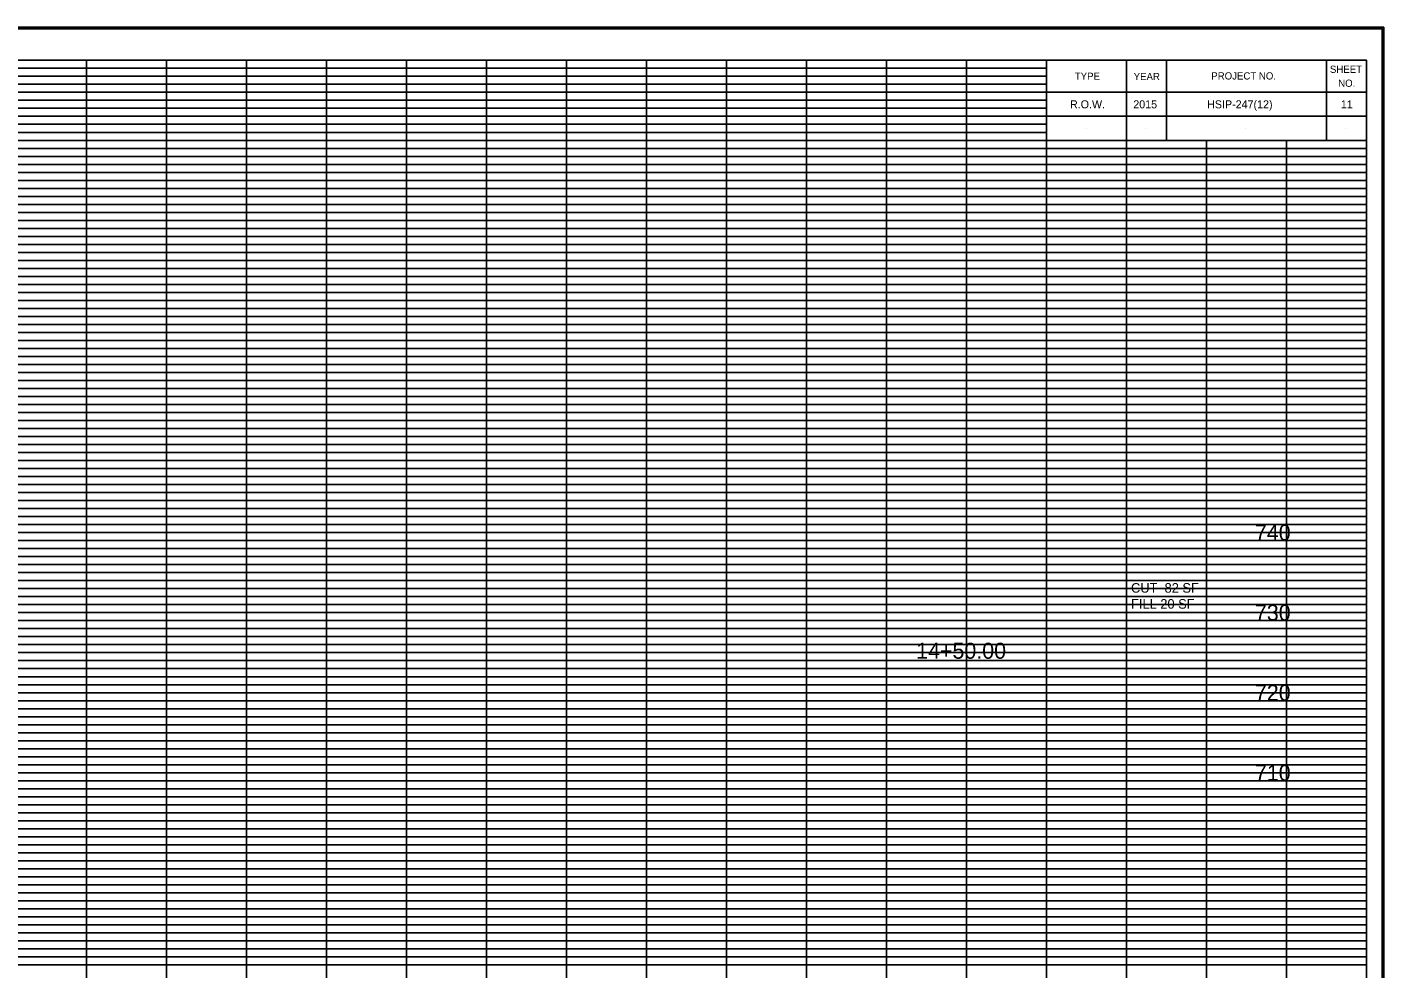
# Model space of a CAD drawing. Extents: x -200 to 1704, y -325 to 2307.
# Drawn here: x 1152.6 to 1322.2, y 1366.5 to 1484.1 of the extents above; entities that cross this region are included whole.
import ezdxf

# ---------------------------------------------------------------- set-up
doc = ezdxf.new("R2010")
doc.units = 0
for name, color, linetype in [('DESIGN - SCRATCH - User 1', 7, 'Continuous'), ('DESIGN - SHEET - Corner Text', 7, 'Continuous'), ('DESIGN - SHEET - Light Grid', 7, 'Continuous'), ('DESIGN - SHEET - Linework', 7, 'Continuous'), ('DESIGN - SHEET - Plot Shape', 7, 'Continuous'), ('DESIGN - TYPICAL - Text', 7, 'Continuous')]:
    doc.layers.add(name, color=color, linetype=linetype)

msp = doc.modelspace()

# ---------------------------------------------------------------- linework, layer by layer
at = {"layer": 'DESIGN - SCRATCH - User 1'}
for p, q in [((1285, 1474.5), (1285, 1474.5)), ((1292.4, 1474.5), (1292.4, 1474.5)), ((1304.9, 1474.5), (1304.9, 1474.5)), ((1317.4, 1474.5), (1317.4, 1474.5)), ((1285, 1471.5), (1285, 1471.5)), ((1292.4, 1471.5), (1292.4, 1471.5)), ((1304.9, 1471.5), (1304.9, 1471.5)), ((1317.4, 1471.5), (1317.4, 1471.5))]:
    msp.add_line(p, q, dxfattribs=at)
at = {"layer": 'DESIGN - SHEET - Light Grid'}
for p, q in [((1080, 1479), (1160, 1479)), ((1160, 1479), (1240, 1479)), ((1240, 1479), (1280, 1479)), ((1080, 1478), (1160, 1478)), ((1160, 1478), (1240, 1478)), ((1240, 1478), (1280, 1478)), ((1080, 1477), (1160, 1477)), ((1080, 1476), (1160, 1476)), ((1160, 1477), (1240, 1477)), ((1160, 1476), (1240, 1476)), ((1240, 1477), (1280, 1477)), ((1240, 1476), (1280, 1476)), ((1080, 1475), (1160, 1475)), ((1080, 1474), (1160, 1474)), ((1160, 1475), (1240, 1475)), ((1160, 1474), (1240, 1474)), ((1240, 1475), (1280, 1475)), ((1240, 1474), (1280, 1474)), ((1080, 1473), (1160, 1473)), ((1080, 1472), (1160, 1472)), ((1160, 1473), (1240, 1473)), ((1160, 1472), (1240, 1472)), ((1240, 1473), (1280, 1473)), ((1240, 1472), (1280, 1472)), ((1080, 1471), (1160, 1471)), ((1160, 1471), (1240, 1471)), ((1240, 1471), (1280, 1471)), ((1080, 1469), (1160, 1469)), ((1160, 1469), (1240, 1469)), ((1240, 1469), (1320, 1469)), ((1080, 1468), (1160, 1468)), ((1080, 1467), (1160, 1467)), ((1160, 1468), (1240, 1468)), ((1160, 1467), (1240, 1467)), ((1240, 1468), (1320, 1468)), ((1240, 1467), (1320, 1467)), ((1080, 1466), (1160, 1466)), ((1160, 1466), (1240, 1466)), ((1240, 1466), (1320, 1466)), ((1080, 1465), (1160, 1465)), ((1080, 1464), (1160, 1464)), ((1160, 1465), (1240, 1465)), ((1160, 1464), (1240, 1464)), ((1240, 1465), (1320, 1465)), ((1240, 1464), (1320, 1464)), ((1080, 1463), (1160, 1463)), ((1080, 1462), (1160, 1462)), ((1160, 1463), (1240, 1463)), ((1160, 1462), (1240, 1462)), ((1240, 1463), (1320, 1463)), ((1240, 1462), (1320, 1462)), ((1080, 1461), (1160, 1461)), ((1160, 1461), (1240, 1461)), ((1240, 1461), (1320, 1461)), ((1080, 1459), (1160, 1459)), ((1160, 1459), (1240, 1459)), ((1240, 1459), (1320, 1459)), ((1080, 1458), (1160, 1458)), ((1080, 1457), (1160, 1457)), ((1160, 1458), (1240, 1458)), ((1160, 1457), (1240, 1457)), ((1240, 1458), (1320, 1458)), ((1240, 1457), (1320, 1457)), ((1080, 1456), (1160, 1456)), ((1080, 1455), (1160, 1455)), ((1160, 1456), (1240, 1456)), ((1160, 1455), (1240, 1455)), ((1240, 1456), (1320, 1456)), ((1240, 1455), (1320, 1455)), ((1080, 1454), (1160, 1454)), ((1160, 1454), (1240, 1454)), ((1240, 1454), (1320, 1454)), ((1080, 1453), (1160, 1453)), ((1080, 1452), (1160, 1452)), ((1160, 1453), (1240, 1453)), ((1160, 1452), (1240, 1452)), ((1240, 1453), (1320, 1453)), ((1240, 1452), (1320, 1452)), ((1080, 1451), (1160, 1451)), ((1160, 1451), (1240, 1451)), ((1240, 1451), (1320, 1451)), ((1080, 1449), (1160, 1449)), ((1160, 1449), (1240, 1449)), ((1240, 1449), (1320, 1449)), ((1080, 1448), (1160, 1448)), ((1080, 1447), (1160, 1447)), ((1160, 1448), (1240, 1448)), ((1160, 1447), (1240, 1447)), ((1240, 1448), (1320, 1448)), ((1240, 1447), (1320, 1447)), ((1080, 1446), (1160, 1446)), ((1080, 1445), (1160, 1445)), ((1160, 1446), (1240, 1446)), ((1160, 1445), (1240, 1445)), ((1240, 1446), (1320, 1446)), ((1240, 1445), (1320, 1445)), ((1080, 1444), (1160, 1444)), ((1160, 1444), (1240, 1444)), ((1240, 1444), (1320, 1444)), ((1080, 1443), (1160, 1443)), ((1080, 1442), (1160, 1442)), ((1160, 1443), (1240, 1443)), ((1160, 1442), (1240, 1442)), ((1240, 1443), (1320, 1443)), ((1240, 1442), (1320, 1442)), ((1080, 1441), (1160, 1441)), ((1160, 1441), (1240, 1441)), ((1240, 1441), (1320, 1441)), ((1080, 1439), (1160, 1439)), ((1160, 1439), (1240, 1439)), ((1240, 1439), (1320, 1439)), ((1080, 1438), (1160, 1438)), ((1080, 1437), (1160, 1437)), ((1160, 1438), (1240, 1438)), ((1160, 1437), (1240, 1437)), ((1240, 1438), (1320, 1438)), ((1240, 1437), (1320, 1437)), ((1080, 1436), (1160, 1436)), ((1080, 1435), (1160, 1435)), ((1160, 1436), (1240, 1436)), ((1160, 1435), (1240, 1435)), ((1240, 1436), (1320, 1436)), ((1240, 1435), (1320, 1435)), ((1080, 1434), (1160, 1434)), ((1080, 1433), (1160, 1433)), ((1160, 1434), (1240, 1434)), ((1160, 1433), (1240, 1433)), ((1240, 1434), (1320, 1434)), ((1240, 1433), (1320, 1433)), ((1080, 1432), (1160, 1432)), ((1160, 1432), (1240, 1432)), ((1240, 1432), (1320, 1432)), ((1080, 1431), (1160, 1431)), ((1160, 1431), (1240, 1431)), ((1240, 1431), (1320, 1431)), ((1080, 1429), (1160, 1429)), ((1080, 1428), (1160, 1428)), ((1160, 1429), (1240, 1429)), ((1160, 1428), (1240, 1428)), ((1240, 1429), (1320, 1429)), ((1240, 1428), (1320, 1428)), ((1080, 1427), (1160, 1427)), ((1160, 1427), (1240, 1427)), ((1240, 1427), (1320, 1427)), ((1080, 1426), (1160, 1426)), ((1080, 1425), (1160, 1425)), ((1160, 1426), (1240, 1426)), ((1160, 1425), (1240, 1425)), ((1240, 1426), (1320, 1426)), ((1240, 1425), (1320, 1425)), ((1080, 1424), (1160, 1424)), ((1080, 1423), (1160, 1423)), ((1160, 1424), (1240, 1424)), ((1160, 1423), (1240, 1423)), ((1240, 1424), (1320, 1424)), ((1240, 1423), (1320, 1423)), ((1080, 1422), (1160, 1422)), ((1160, 1422), (1240, 1422)), ((1240, 1422), (1320, 1422)), ((1080, 1421), (1160, 1421)), ((1160, 1421), (1240, 1421)), ((1240, 1421), (1320, 1421)), ((1080, 1419), (1160, 1419)), ((1080, 1418), (1160, 1418)), ((1160, 1419), (1240, 1419)), ((1160, 1418), (1240, 1418)), ((1240, 1419), (1320, 1419)), ((1240, 1418), (1320, 1418)), ((1080, 1417), (1160, 1417)), ((1080, 1416), (1160, 1416)), ((1160, 1417), (1240, 1417)), ((1160, 1416), (1240, 1416)), ((1240, 1417), (1320, 1417)), ((1240, 1416), (1320, 1416)), ((1080, 1415), (1160, 1415)), ((1160, 1415), (1240, 1415)), ((1240, 1415), (1320, 1415)), ((1080, 1414), (1160, 1414)), ((1080, 1413), (1160, 1413)), ((1160, 1414), (1240, 1414)), ((1160, 1413), (1240, 1413)), ((1240, 1414), (1320, 1414)), ((1240, 1413), (1320, 1413)), ((1080, 1412), (1160, 1412)), ((1080, 1411), (1160, 1411)), ((1160, 1412), (1240, 1412)), ((1160, 1411), (1240, 1411)), ((1240, 1412), (1320, 1412)), ((1240, 1411), (1320, 1411)), ((1080, 1409), (1160, 1409)), ((1080, 1408), (1160, 1408)), ((1160, 1409), (1240, 1409)), ((1160, 1408), (1240, 1408)), ((1240, 1409), (1320, 1409)), ((1240, 1408), (1320, 1408)), ((1080, 1407), (1160, 1407)), ((1080, 1406), (1160, 1406)), ((1160, 1407), (1240, 1407)), ((1160, 1406), (1240, 1406)), ((1240, 1407), (1320, 1407)), ((1240, 1406), (1320, 1406)), ((1080, 1405), (1160, 1405)), ((1160, 1405), (1240, 1405)), ((1240, 1405), (1320, 1405)), ((1080, 1404), (1160, 1404)), ((1080, 1403), (1160, 1403)), ((1160, 1404), (1240, 1404)), ((1160, 1403), (1240, 1403)), ((1240, 1404), (1320, 1404)), ((1240, 1403), (1320, 1403)), ((1080, 1402), (1160, 1402)), ((1080, 1401), (1160, 1401)), ((1160, 1402), (1240, 1402)), ((1160, 1401), (1240, 1401)), ((1240, 1402), (1320, 1402)), ((1240, 1401), (1320, 1401)), ((1080, 1399), (1160, 1399)), ((1080, 1398), (1160, 1398)), ((1160, 1399), (1240, 1399)), ((1160, 1398), (1240, 1398)), ((1240, 1399), (1320, 1399)), ((1240, 1398), (1320, 1398)), ((1080, 1397), (1160, 1397)), ((1080, 1396), (1160, 1396)), ((1160, 1397), (1240, 1397)), ((1160, 1396), (1240, 1396)), ((1240, 1397), (1320, 1397)), ((1240, 1396), (1320, 1396)), ((1080, 1395), (1160, 1395)), ((1080, 1394), (1160, 1394)), ((1160, 1395), (1240, 1395)), ((1160, 1394), (1240, 1394)), ((1240, 1395), (1320, 1395)), ((1240, 1394), (1320, 1394)), ((1080, 1393), (1160, 1393)), ((1160, 1393), (1240, 1393)), ((1240, 1393), (1320, 1393)), ((1080, 1392), (1160, 1392)), ((1080, 1391), (1160, 1391)), ((1160, 1392), (1240, 1392)), ((1160, 1391), (1240, 1391)), ((1240, 1392), (1320, 1392)), ((1240, 1391), (1320, 1391)), ((1080, 1389), (1160, 1389)), ((1160, 1389), (1240, 1389)), ((1240, 1389), (1320, 1389)), ((1080, 1388), (1160, 1388)), ((1160, 1388), (1240, 1388)), ((1240, 1388), (1320, 1388)), ((1080, 1387), (1160, 1387)), ((1080, 1386), (1160, 1386)), ((1160, 1387), (1240, 1387)), ((1160, 1386), (1240, 1386)), ((1240, 1387), (1320, 1387)), ((1240, 1386), (1320, 1386)), ((1080, 1385), (1160, 1385)), ((1080, 1384), (1160, 1384)), ((1160, 1385), (1240, 1385)), ((1160, 1384), (1240, 1384)), ((1240, 1385), (1320, 1385)), ((1240, 1384), (1320, 1384)), ((1080, 1383), (1160, 1383)), ((1160, 1383), (1240, 1383)), ((1240, 1383), (1320, 1383)), ((1080, 1382), (1160, 1382)), ((1080, 1381), (1160, 1381)), ((1160, 1382), (1240, 1382)), ((1160, 1381), (1240, 1381)), ((1240, 1382), (1320, 1382)), ((1240, 1381), (1320, 1381)), ((1080, 1379), (1160, 1379)), ((1160, 1379), (1240, 1379)), ((1240, 1379), (1320, 1379)), ((1080, 1378), (1160, 1378)), ((1080, 1377), (1160, 1377)), ((1160, 1378), (1240, 1378)), ((1160, 1377), (1240, 1377)), ((1240, 1378), (1320, 1378)), ((1240, 1377), (1320, 1377)), ((1080, 1376), (1160, 1376)), ((1160, 1376), (1240, 1376)), ((1240, 1376), (1320, 1376)), ((1080, 1375), (1160, 1375)), ((1080, 1374), (1160, 1374)), ((1160, 1375), (1240, 1375)), ((1160, 1374), (1240, 1374)), ((1240, 1375), (1320, 1375)), ((1240, 1374), (1320, 1374)), ((1080, 1373), (1160, 1373)), ((1080, 1372), (1160, 1372)), ((1160, 1373), (1240, 1373)), ((1160, 1372), (1240, 1372)), ((1240, 1373), (1320, 1373)), ((1240, 1372), (1320, 1372)), ((1080, 1371), (1160, 1371)), ((1160, 1371), (1240, 1371)), ((1240, 1371), (1320, 1371)), ((1080, 1369), (1160, 1369)), ((1160, 1369), (1240, 1369)), ((1240, 1369), (1320, 1369)), ((1080, 1368), (1160, 1368)), ((1080, 1367), (1160, 1367)), ((1160, 1368), (1240, 1368)), ((1160, 1367), (1240, 1367)), ((1240, 1368), (1320, 1368)), ((1240, 1367), (1320, 1367))]:
    msp.add_line(p, q, dxfattribs=at)
at = {"layer": 'DESIGN - SHEET - Linework'}
for p, q in [((981.77, 1484.14), (1322.17, 1484.14)), ((1322.17, 1484.14), (1322.17, 1265.86)), ((1160, 1270), (1160, 1480)), ((1170, 1270), (1170, 1480)), ((1180, 1270), (1180, 1480)), ((1190, 1270), (1190, 1480)), ((1200, 1270), (1200, 1480)), ((1210, 1270), (1210, 1480)), ((1220, 1270), (1220, 1480)), ((1230, 1270), (1230, 1480)), ((1240, 1270), (1240, 1480)), ((1250, 1270), (1250, 1480)), ((1260, 1270), (1260, 1480)), ((1270, 1270), (1270, 1480)), ((1000, 1470), (1280, 1470)), ((1280, 1270), (1280, 1470)), ((1290, 1270), (1290, 1470)), ((1300, 1270), (1300, 1470)), ((1310, 1270), (1310, 1470)), ((1000, 1460), (1320, 1460)), ((1000, 1450), (1320, 1450)), ((1000, 1440), (1320, 1440)), ((1000, 1430), (1320, 1430)), ((1000, 1420), (1320, 1420)), ((1000, 1410), (1320, 1410)), ((1000, 1400), (1320, 1400)), ((1000, 1390), (1320, 1390)), ((1000, 1380), (1320, 1380)), ((1000, 1370), (1320, 1370))]:
    msp.add_line(p, q, dxfattribs=at)
for points in [[(1000, 1480), (1000, 1270), (1320, 1270), (1320, 1480), (1000, 1480)], [(1280, 1480), (1280, 1470), (1320, 1470), (1320, 1480), (1315, 1480), (1315, 1470), (1295, 1470), (1295, 1480), (1290, 1480), (1290, 1470), (1320, 1470), (1280, 1470), (1280, 1473), (1320, 1473), (1320, 1476), (1280, 1476)]]:
    msp.add_lwpolyline(points, dxfattribs=at)
at = {"layer": 'DESIGN - SHEET - Plot Shape'}
for points in [[(981.97, 1483.94), (1321.97, 1483.94), (1321.97, 1266.06), (981.97, 1266.06)], [(991.5, 1480), (1320, 1480), (1320, 1267.5), (991.5, 1267.5)]]:
    msp.add_lwpolyline(points, close=True, dxfattribs=at)

# ---------------------------------------------------------------- texts
at = {"layer": 'DESIGN - SHEET - Corner Text'}
for s, height, p in [('SHEET', 0.9, (1315.43, 1478.43)), ('TYPE', 0.9, (1283.54, 1477.56)), ('YEAR', 0.9, (1290.9, 1477.52)), ('PROJECT NO.', 0.9, (1300.6, 1477.6)), ('NO.', 0.9, (1316.46, 1476.69)), ('R.O.W.', 1, (1282.94, 1474)), ('2015', 1, (1290.85, 1474)), ('HSIP-247(12)', 1, (1300.08, 1474)), ('11', 1, (1316.79, 1474))]:
    msp.add_text(s, height=height, dxfattribs=at).set_placement(p)
at = {"layer": 'DESIGN - TYPICAL - Text'}
for s, height, p in [('     740     ', 2, (1302.34, 1420)), ('CUT  82 SF', 1.2, (1290.57, 1413.49)), ('FILL 20 SF', 1.2, (1290.57, 1411.49)), ('     730     ', 2, (1302.34, 1410)), ('     14+50.00     ', 2, (1260, 1405.24)), ('     720     ', 2, (1302.34, 1400)), ('     710     ', 2, (1302.34, 1390))]:
    msp.add_text(s, height=height, dxfattribs=at).set_placement(p)

doc.saveas('drawing.dxf')
